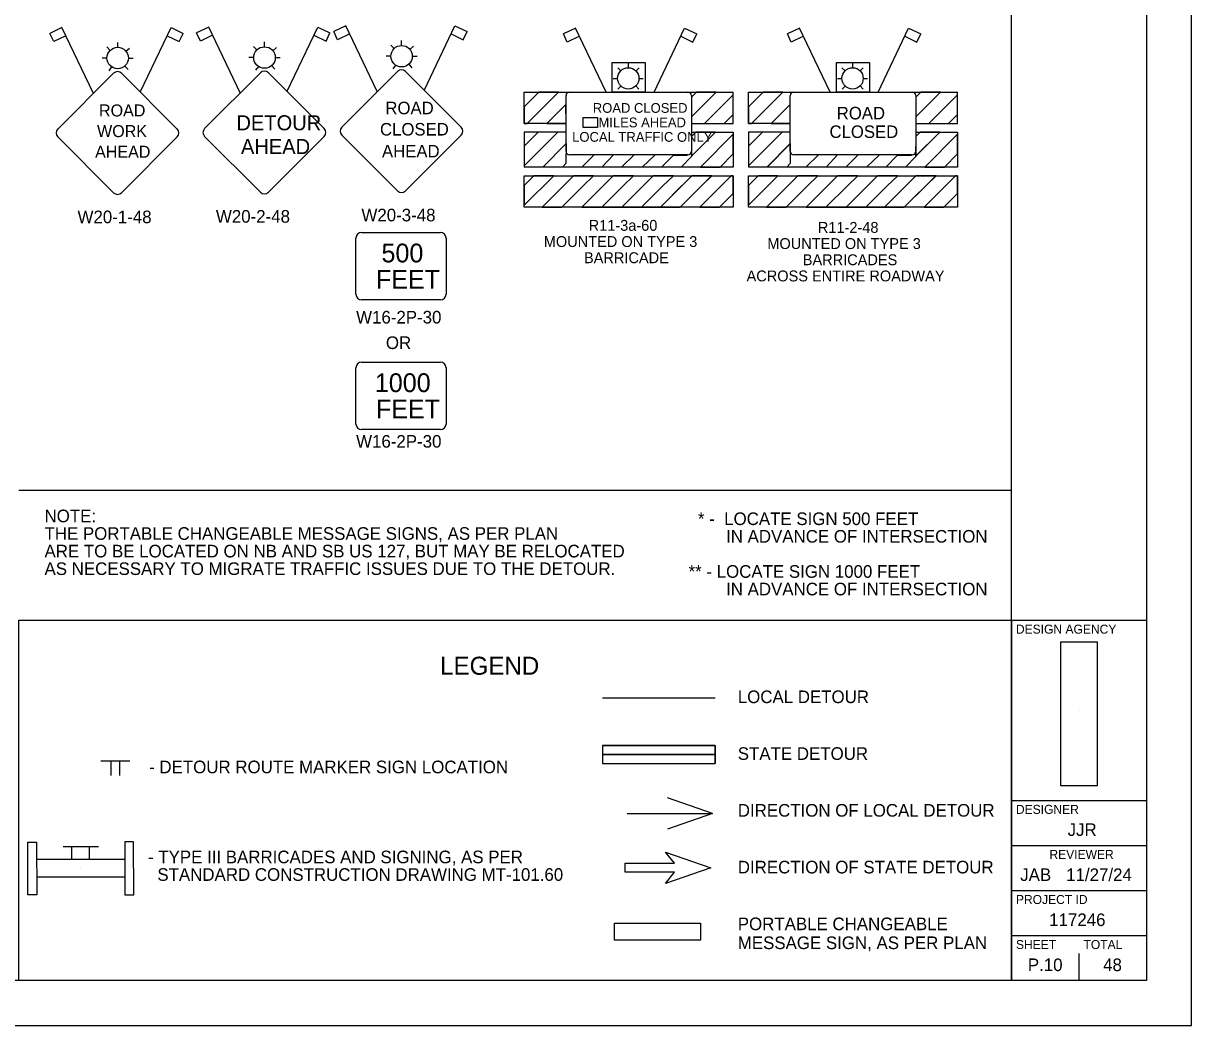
# Model space of a CAD drawing. Extents: x 1341221 to 1914484, y 79347 to 658398.
# Drawn here: x 1435873 to 1494221, y 559398 to 609451 of the extents above; entities that cross this region are included whole.
import ezdxf

# ---------------------------------------------------------------- set-up
doc = ezdxf.new("R2010")
doc.units = 0
for name, color, linetype in [('GM_X_County', 7, 'Continuous'), ('GM_X_County_Road_Text', 7, 'Continuous'), ('GM_X_Minor_Lake', 7, 'Continuous'), ('GM_X_Minor_Lake_Text', 7, 'Continuous'), ('GM_X_Minor_River', 7, 'Continuous'), ('GM_X_Minor_River_Text', 7, 'Continuous'), ('GM_X_State_Location', 7, 'Continuous'), ('GM_X_Township_Road_Text', 7, 'Continuous')]:
    doc.layers.add(name, color=color, linetype=linetype)

msp = doc.modelspace()

# ---------------------------------------------------------------- linework, layer by layer
at = {"layer": 'GM_X_County'}
for p, q in [((1437800, 609239), (1437194, 608949)), ((1439371, 605952), (1437800, 609239)), ((1441721, 606043), (1443249, 609239)), ((1443249, 609239), (1443856, 608949)), ((1445132, 609265), (1444525, 608975)), ((1446703, 605978), (1445132, 609265)), ((1449053, 606069), (1450581, 609265)), ((1450581, 609265), (1451187, 608975)), ((1451980, 609332), (1451373, 609042)), ((1453551, 606045), (1451980, 609332)), ((1455901, 606136), (1457428, 609332)), ((1457428, 609332), (1458035, 609042)), ((1463450, 609217), (1462844, 608927)), ((1464978, 606022), (1463450, 609217)), ((1467371, 606022), (1468899, 609217)), ((1468899, 609217), (1469506, 608927)), ((1474639, 609214), (1474033, 608924)), ((1476167, 606019), (1474639, 609214)), ((1478560, 606019), (1480088, 609214)), ((1480088, 609214), (1480695, 608924)), ((1437389, 608541), (1437194, 608949)), ((1437995, 608831), (1437389, 608541)), ((1443054, 608831), (1443661, 608541)), ((1443661, 608541), (1443856, 608949)), ((1444720, 608567), (1444525, 608975)), ((1445327, 608857), (1444720, 608567)), ((1450386, 608857), (1450992, 608567)), ((1450992, 608567), (1451187, 608975)), ((1451568, 608634), (1451373, 609042)), ((1452175, 608924), (1451568, 608634)), ((1454763, 608347), (1454763, 608588)), ((1457233, 608924), (1457840, 608634)), ((1457840, 608634), (1458035, 609042)), ((1463039, 608520), (1462844, 608927)), ((1463645, 608810), (1463039, 608520)), ((1468704, 608810), (1469311, 608520)), ((1469311, 608520), (1469506, 608927)), ((1474228, 608516), (1474033, 608924)), ((1474834, 608806), (1474228, 608516)), ((1479893, 608806), (1480500, 608516)), ((1480500, 608516), (1480695, 608924)), ((1440210, 608102), (1440041, 608275)), ((1440584, 608254), (1440584, 608496)), ((1440995, 608062), (1441180, 608216)), ((1447541, 608128), (1447373, 608300)), ((1447916, 608280), (1447916, 608521)), ((1448327, 608087), (1448512, 608242)), ((1454389, 608195), (1454221, 608367)), ((1455175, 608154), (1455360, 608309)), ((1440048, 607719), (1439807, 607719)), ((1441120, 607719), (1441361, 607719)), ((1447380, 607744), (1447139, 607744)), ((1448451, 607744), (1448693, 607744)), ((1454227, 607811), (1453986, 607811)), ((1455120, 607411), (1455280, 607231)), ((1455299, 607811), (1455540, 607811)), ((1466085, 607448), (1466087, 607229)), ((1477286, 607448), (1477288, 607230)), ((1440278, 607279), (1440140, 607081)), ((1440940, 607319), (1441101, 607139)), ((1447609, 607305), (1447472, 607107)), ((1448272, 607344), (1448433, 607164)), ((1454457, 607371), (1454319, 607173)), ((1465556, 607230), (1465709, 607077)), ((1466466, 607072), (1466620, 607228)), ((1476757, 607230), (1476910, 607077)), ((1477668, 607073), (1477821, 607228)), ((1465335, 606702), (1465553, 606703)), ((1465561, 606167), (1465715, 606323)), ((1466461, 606325), (1466614, 606172)), ((1466615, 606702), (1466833, 606704)), ((1476536, 606702), (1476755, 606703)), ((1476762, 606167), (1476916, 606323)), ((1477662, 606325), (1477815, 606172)), ((1477816, 606702), (1478035, 606704)), ((1460885, 605287), (1461613, 606018)), ((1461613, 606018), (1460885, 605287)), ((1461034, 604448), (1462599, 606018)), ((1461034, 604448), (1462599, 606018)), ((1462975, 603059), (1462975, 605847)), ((1463149, 606019), (1469067, 606018)), ((1463150, 606022), (1469065, 606022)), ((1468542, 606017), (1471327, 606018)), ((1469240, 605763), (1469491, 606018)), ((1469491, 606018), (1469240, 605763)), ((1469240, 605844), (1469240, 603060)), ((1469240, 605763), (1469241, 604780)), ((1469241, 604780), (1470478, 606018)), ((1469241, 604780), (1470478, 606018)), ((1470478, 606018), (1469491, 606018)), ((1469896, 604450), (1471329, 605886)), ((1471329, 605886), (1469896, 604450)), ((1471328, 604447), (1471327, 606018)), ((1471327, 604900), (1471329, 605886)), ((1472086, 605287), (1472814, 606018)), ((1472814, 606018), (1472086, 605287)), ((1472235, 604449), (1473801, 606018)), ((1472235, 604449), (1473801, 606018)), ((1474176, 603059), (1474177, 605847)), ((1474350, 606019), (1480268, 606018)), ((1474351, 606022), (1480266, 606022)), ((1479743, 606017), (1482528, 606018)), ((1480441, 605763), (1480693, 606018)), ((1480693, 606018), (1480441, 605763)), ((1480441, 605845), (1480441, 603060)), ((1480441, 605763), (1480442, 604780)), ((1480442, 604780), (1481679, 606018)), ((1480442, 604780), (1481679, 606018)), ((1481679, 606018), (1480693, 606018)), ((1481097, 604450), (1482530, 605886)), ((1482530, 605886), (1481097, 604450)), ((1482530, 604447), (1482528, 606018)), ((1482528, 604900), (1482530, 605886)), ((1462974, 605407), (1462018, 604450)), ((1462018, 604450), (1462974, 605407)), ((1462976, 604448), (1462974, 605407)), ((1474175, 605407), (1473219, 604450)), ((1473219, 604450), (1474175, 605407)), ((1474177, 604448), (1474175, 605407)), ((1470879, 604448), (1471327, 604900)), ((1470879, 604448), (1471327, 604900)), ((1482080, 604448), (1482528, 604900)), ((1482080, 604448), (1482528, 604900)), ((1462973, 604015), (1460887, 604013)), ((1460887, 603317), (1461584, 604015)), ((1461584, 604015), (1460887, 603317)), ((1460887, 604013), (1460888, 602274)), ((1460888, 602333), (1462567, 604013)), ((1460888, 602333), (1462567, 604013)), ((1462567, 604013), (1461584, 604015)), ((1469239, 602811), (1470445, 604014)), ((1469239, 603797), (1469459, 604013)), ((1469240, 604449), (1471328, 604447)), ((1469687, 602273), (1471327, 603914)), ((1471327, 603914), (1469687, 602273)), ((1469896, 604450), (1470879, 604448)), ((1472088, 603317), (1472785, 604015)), ((1472785, 604015), (1472088, 603317)), ((1474174, 604015), (1472089, 604013)), ((1472089, 602334), (1473768, 604014)), ((1472089, 602334), (1473768, 604014)), ((1472089, 604013), (1472089, 602274)), ((1473768, 604014), (1472785, 604015)), ((1480440, 603797), (1480660, 604014)), ((1480441, 602811), (1481646, 604014)), ((1480442, 604449), (1482530, 604447)), ((1480888, 602273), (1482528, 603914)), ((1482528, 603914), (1480888, 602273)), ((1481097, 604450), (1482080, 604448)), ((1482530, 604013), (1482530, 602275)), ((1460887, 603317), (1460888, 602333)), ((1461811, 602273), (1462973, 603438)), ((1472088, 603317), (1472089, 602334)), ((1473013, 602273), (1474174, 603438)), ((1469066, 602885), (1463148, 602885)), ((1470673, 602274), (1471328, 602930)), ((1470673, 602274), (1471328, 602930)), ((1480267, 602885), (1474349, 602886)), ((1481874, 602274), (1482529, 602930)), ((1481874, 602274), (1482529, 602930)), ((1468178, 602273), (1460888, 602274)), ((1469206, 602273), (1468178, 602273)), ((1479379, 602273), (1472089, 602274)), ((1480407, 602273), (1479379, 602273)), ((1460886, 600364), (1462361, 601840)), ((1460886, 600364), (1462361, 601840)), ((1460886, 601351), (1461375, 601839)), ((1461375, 601839), (1460886, 601351)), ((1461780, 600274), (1463345, 601841)), ((1463345, 601841), (1461780, 600274)), ((1464354, 601838), (1463345, 601841)), ((1463773, 600272), (1465338, 601839)), ((1465338, 601839), (1463773, 600272)), ((1463833, 601342), (1464354, 601838)), ((1466347, 601836), (1465338, 601839)), ((1465766, 600270), (1467330, 601837)), ((1467330, 601837), (1465766, 600270)), ((1465825, 601341), (1466347, 601836)), ((1468340, 601835), (1467330, 601837)), ((1469251, 601843), (1467687, 600276)), ((1467818, 601339), (1468340, 601835)), ((1468284, 600870), (1469253, 601839)), ((1468669, 600274), (1470240, 601839)), ((1470260, 601840), (1469251, 601843)), ((1469656, 600275), (1471223, 601838)), ((1471223, 601838), (1469656, 600275)), ((1469739, 601344), (1470260, 601840)), ((1472087, 600364), (1473562, 601840)), ((1472087, 600364), (1473562, 601840)), ((1472087, 601351), (1472576, 601839)), ((1472576, 601839), (1472087, 601351)), ((1472981, 600274), (1474546, 601841)), ((1474546, 601841), (1472981, 600274)), ((1475555, 601838), (1474546, 601841)), ((1474974, 600272), (1476539, 601839)), ((1476539, 601839), (1474974, 600272)), ((1475034, 601342), (1475555, 601838)), ((1477548, 601836), (1476539, 601839)), ((1476967, 600271), (1478532, 601838)), ((1478532, 601838), (1476967, 600271)), ((1477027, 601341), (1477548, 601836)), ((1479541, 601835), (1478532, 601838)), ((1480452, 601843), (1478888, 600276)), ((1479019, 601339), (1479541, 601835)), ((1479485, 600870), (1480454, 601839)), ((1479870, 600274), (1481441, 601840)), ((1481461, 601840), (1480452, 601843)), ((1480857, 600275), (1482424, 601838)), ((1482424, 601838), (1480857, 600275)), ((1480940, 601345), (1481461, 601840)), ((1462763, 600272), (1463833, 601342)), ((1464756, 600270), (1465825, 601341)), ((1466748, 600269), (1467818, 601339)), ((1468669, 600274), (1469739, 601344)), ((1473964, 600272), (1475034, 601342)), ((1475957, 600271), (1477027, 601341)), ((1477950, 600269), (1479019, 601339)), ((1479870, 600274), (1480940, 601345)), ((1470641, 600272), (1471327, 600961)), ((1470641, 600272), (1471327, 600961)), ((1481843, 600272), (1482528, 600961)), ((1481843, 600272), (1482528, 600961)), ((1461780, 600274), (1462763, 600272)), ((1463773, 600272), (1464756, 600270)), ((1464008, 600276), (1468005, 600273)), ((1465766, 600270), (1466748, 600269)), ((1467687, 600276), (1468669, 600274)), ((1472981, 600274), (1473964, 600272)), ((1474974, 600272), (1475957, 600271)), ((1475209, 600277), (1479206, 600274)), ((1476967, 600271), (1477950, 600269)), ((1478888, 600276), (1479870, 600274)), ((1464804, 575773), (1470429, 575773)), ((1464804, 573388), (1470429, 573388)), ((1464804, 573388), (1464804, 572488)), ((1470429, 573388), (1470429, 572488)), ((1464804, 572488), (1470429, 572488)), ((1470299, 569986), (1468049, 569205))]:
    msp.add_line(p, q, dxfattribs=at)
for points in [[(1465288, 607489), (1466926, 607489), (1466926, 606022), (1465288, 606022)], [(1476489, 607489), (1478128, 607489), (1478128, 606022), (1476489, 606022)], [(1463836, 604754), (1464542, 604754), (1464542, 604255), (1463836, 604255)], [(1469459, 604013), (1469239, 603797), (1469235, 602818), (1470445, 604014)], [(1480660, 604014), (1480440, 603797), (1480436, 602818), (1481646, 604014)], [(1461809, 602276), (1462976, 603449), (1462969, 602446), (1462798, 602273)], [(1473010, 602276), (1474177, 603450), (1474170, 602446), (1473999, 602273)], [(1464399, 602897), (1465355, 602899), (1464765, 602274), (1463757, 602274)], [(1465752, 602273), (1466389, 602902), (1467431, 602888), (1466781, 602273)], [(1468336, 602876), (1469016, 602876), (1469121, 602895), (1469182, 602935), (1469219, 602969), (1469237, 603026), (1469238, 602804), (1468722, 602273), (1467745, 602273)], [(1475600, 602897), (1476556, 602899), (1475966, 602274), (1474958, 602274)], [(1476953, 602274), (1477590, 602902), (1478632, 602888), (1477982, 602274)], [(1479537, 602876), (1480218, 602876), (1480323, 602895), (1480383, 602935), (1480420, 602969), (1480439, 603026), (1480439, 602805), (1479923, 602273), (1478946, 602273)], [(1489522, 571384), (1489522, 578543), (1487671, 578543), (1487671, 571384)], [(1470429, 573388), (1464804, 573388), (1464804, 572938), (1470429, 572938)], [(1464804, 572488), (1470429, 572488), (1470429, 572938), (1464804, 572938)]]:
    msp.add_lwpolyline(points, close=True, dxfattribs=at)
for points in [[(1460886, 606017), (1463670, 606018)], [(1462976, 604448), (1460888, 604450), (1460886, 606017)], [(1462599, 606018), (1461613, 606018)], [(1472087, 606018), (1474871, 606018)], [(1474177, 604448), (1472089, 604450), (1472087, 606018)], [(1473801, 606018), (1472814, 606018)], [(1460885, 605287), (1460888, 604450), (1461034, 604448)], [(1472086, 605287), (1472089, 604450), (1472235, 604449)], [(1462018, 604450), (1462976, 604448)], [(1469241, 604015), (1471329, 604013), (1471329, 602274), (1469206, 602273)], [(1471328, 602930), (1471327, 603914)], [(1473219, 604450), (1474177, 604448)], [(1480442, 604015), (1482530, 604013), (1482530, 602275), (1480407, 602273)], [(1482529, 602930), (1482528, 603914)], [(1469687, 602273), (1470673, 602274)], [(1480888, 602273), (1481874, 602274)], [(1460887, 601837), (1463835, 601838)], [(1468110, 600273), (1460887, 600274), (1460887, 601837)], [(1462361, 601840), (1461375, 601839)], [(1463245, 601838), (1471328, 601838), (1471329, 600274), (1468014, 600273)], [(1471327, 600961), (1471328, 601838), (1471223, 601838)], [(1472088, 601837), (1475036, 601838)], [(1479311, 600273), (1472088, 600274), (1472088, 601837)], [(1473562, 601840), (1472576, 601839)], [(1474446, 601838), (1482530, 601838), (1482530, 600274), (1479216, 600273)], [(1482528, 600961), (1482530, 601838), (1482424, 601838)], [(1460886, 601351), (1460886, 600364)], [(1472087, 601351), (1472087, 600364)], [(1469656, 600275), (1470641, 600272)], [(1480857, 600275), (1481843, 600272)], [(1466024, 569986), (1470299, 569986), (1468049, 570767)]]:
    msp.add_lwpolyline(points, dxfattribs=at)
for centre, radius in [((1440584, 607719), 536), ((1447916, 607744), 536), ((1454763, 607811), 536), ((1466085, 606701), 532), ((1477286, 606701), 532)]:
    msp.add_circle(centre, radius, dxfattribs=at)
for centre, start, end in [((1463149, 605845), 89.99972, 179.99972), ((1469066, 605845), 359.99972, 89.99972), ((1474350, 605846), 89.99972, 179.99972), ((1480268, 605846), 359.99972, 89.99972), ((1463149, 603061), 179.99972, 269.99972), ((1469066, 603061), 269.99972, 359.99972), ((1474350, 603061), 179.99972, 269.99972), ((1480268, 603061), 269.99972, 359.99972)]:
    msp.add_arc(centre, 174, start, end, dxfattribs=at)
at = {"layer": 'GM_X_County_Road_Text'}
for points in [[(1437594, 604175), (1440379, 606960)], [(1440776, 606960), (1443561, 604175)], [(1444926, 604201), (1447711, 606985)], [(1448108, 606985), (1450893, 604201)], [(1451774, 604268), (1454558, 607052)], [(1454956, 607052), (1457740, 604268)], [(1440379, 600993), (1437594, 603778)], [(1443561, 603778), (1440776, 600993)], [(1447711, 601019), (1444926, 603803)], [(1450893, 603803), (1448108, 601019)], [(1454558, 601086), (1451774, 603870)], [(1457740, 603870), (1454956, 601086)]]:
    msp.add_lwpolyline(points, dxfattribs=at)
msp.add_lwpolyline([(1465393, 564517), (1469696, 564517), (1469696, 563672), (1465393, 563672)], close=True, dxfattribs=at)
for centre, start, end in [((1440578, 606761), 45, 135), ((1447909, 606786), 45, 135), ((1454757, 606853), 45, 135), ((1437793, 603977), 135, 225), ((1443362, 603977), 315, 45), ((1445125, 604002), 135, 225), ((1450694, 604002), 315, 45), ((1451973, 604069), 135, 225), ((1457541, 604069), 315, 45), ((1440578, 601192), 225, 315), ((1447909, 601218), 225, 315), ((1454757, 601285), 225, 315)]:
    msp.add_arc(centre, 281, start, end, dxfattribs=at)
at = {"layer": 'GM_X_Minor_Lake'}
for p, q in [((1488596, 575148), (1488596, 575148)), ((1488596, 561648), (1488596, 562998)), ((1486908, 562436), (1486908, 562436))]:
    msp.add_line(p, q, dxfattribs=at)
at = {"layer": 'GM_X_Minor_Lake_Text'}
for p, q in [((1485221, 561648), (1485221, 656148)), ((1435650, 586144), (1485221, 586144)), ((1485221, 579648), (1491971, 579648)), ((1485221, 570648), (1491971, 570648)), ((1485221, 568398), (1491971, 568398)), ((1485221, 566148), (1491971, 566148)), ((1485221, 563898), (1491971, 563898))]:
    msp.add_line(p, q, dxfattribs=at)
for points in [[(1347971, 656148), (1491971, 656148), (1491971, 561648), (1347971, 561648)], [(1435649, 579648), (1485221, 579648), (1485221, 561648), (1435649, 561648)]]:
    msp.add_lwpolyline(points, close=True, dxfattribs=at)
at = {"layer": 'GM_X_Minor_River'}
for p, q in [((1439742, 572618), (1441182, 572618)), ((1440246, 572618), (1440246, 571898)), ((1440462, 572618), (1440462, 572618)), ((1440462, 572618), (1440462, 572618)), ((1440678, 572618), (1440678, 571898))]:
    msp.add_line(p, q, dxfattribs=at)
for points in [[(1452483, 595919), (1452483, 598731)], [(1452765, 599013), (1456702, 599013)], [(1456983, 598731), (1456983, 595919)], [(1456702, 595638), (1452765, 595638)], [(1452483, 589443), (1452483, 592256)], [(1452765, 592537), (1456702, 592537)], [(1456983, 592256), (1456983, 589443)], [(1456702, 589162), (1452765, 589162)]]:
    msp.add_lwpolyline(points, dxfattribs=at)
for centre, start, end in [((1452765, 598731), 90, 180), ((1456702, 598731), 0, 90), ((1452765, 595919), 180, 270), ((1456702, 595919), 270, 0), ((1452765, 592256), 90, 180), ((1456702, 592256), 0, 90), ((1452765, 589443), 180, 270), ((1456702, 589443), 270, 0)]:
    msp.add_arc(centre, 281, start, end, dxfattribs=at)
at = {"layer": 'GM_X_Minor_River_Text'}
msp.add_lwpolyline([(1341221, 559398), (1494221, 559398), (1494221, 658398), (1341221, 658398)], close=True, dxfattribs=at)
at = {"layer": 'GM_X_State_Location'}
msp.add_lwpolyline([(1470429, 572938), (1464804, 572938)], dxfattribs=at)
at = {"layer": 'GM_X_Township_Road_Text'}
for p, q in [((1437858, 568349), (1439619, 568352)), ((1438299, 567689), (1438298, 568350)), ((1439180, 567691), (1439179, 568351)), ((1468400, 567507), (1467950, 568063)), ((1467950, 568063), (1470200, 567282)), ((1440942, 567693), (1436537, 567687)), ((1438740, 567249), (1438740, 567249)), ((1465925, 567057), (1465925, 567507)), ((1465925, 567507), (1468400, 567507)), ((1465925, 567282), (1465925, 567282)), ((1470200, 567282), (1467950, 566501)), ((1470200, 567282), (1470200, 567282)), ((1440943, 566812), (1436539, 566806)), ((1468400, 567057), (1465925, 567057)), ((1467950, 566501), (1468400, 567057))]:
    msp.add_line(p, q, dxfattribs=at)
for points in [[(1436099, 565924), (1436096, 568567), (1436536, 568568), (1436540, 565925)], [(1441385, 565932), (1441381, 568575), (1440941, 568574), (1440944, 565931)]]:
    msp.add_lwpolyline(points, close=True, dxfattribs=at)

# ---------------------------------------------------------------- texts
at = {"layer": 'GM_X_County'}
for s, height, p in [('ROAD CLOSED', 485.96, (1464312, 604984)), ('ROAD', 624.1, (1476496, 604656)), ('   MILES AHEAD', 485.96, (1464053, 604261)), ('LOCAL TRAFFIC ONLY', 485.96, (1463282, 603538)), ('CLOSED', 624.1, (1476135, 603728)), ('R11-3a-60', 543, (1464106, 599091)), ('R11-2-48', 543, (1475554, 598990)), ('MOUNTED ON TYPE 3', 543.04, (1461865, 598283)), ('MOUNTED ON TYPE 3', 543.04, (1473029, 598182)), ('BARRICADE ', 543, (1463873, 597475)), ('BARRICADES ', 543.04, (1474799, 597374)), ('ACROSS ENTIRE ROADWAY', 543.04, (1471992, 596566))]:
    msp.add_text(s, height=height, rotation=359.99972, dxfattribs=at).set_placement(p)
for s, height, p in [('OR', 630, (1453978, 593187)), ('LEGEND', 900, (1456688, 576921)), ('LOCAL DETOUR', 630, (1471554, 575505)), ('STATE DETOUR', 630, (1471554, 572670)), ('DIRECTION OF LOCAL DETOUR', 630, (1471554, 569835)), ('DIRECTION OF STATE DETOUR', 630, (1471554, 567000)), ('PORTABLE CHANGEABLE ', 630, (1471554, 564165)), ('MESSAGE SIGN, AS PER PLAN', 630, (1471554, 563220))]:
    msp.add_text(s, height=height, dxfattribs=at).set_placement(p)
at = {"layer": 'GM_X_County_Road_Text'}
for s, height, p in [('ROAD', 599.7, (1439651, 604802)), ('ROAD', 625, (1453953, 604912)), ('DETOUR', 750, (1446515, 604111)), ('CLOSED', 625, (1453685, 603850)), ('WORK', 599.7, (1439553, 603770)), ('AHEAD', 599.7, (1439455, 602740)), ('AHEAD', 750, (1446740, 602924)), ('AHEAD', 625, (1453783, 602756)), ('W20-1-48', 630, (1438578, 599471)), ('W20-2-48', 630, (1445490, 599497)), ('W20-3-48', 630, (1452758, 599563)), ('W16-2P-30', 630, (1452492, 594462)), ('W16-2P-30', 630, (1452492, 588262)), ('NOTE:', 630, (1436929, 584537)), ('  * -  LOCATE SIGN 500 FEET', 630, (1469096, 584397)), ('THE PORTABLE CHANGEABLE MESSAGE SIGNS, AS PER PLAN', 630, (1436929, 583659)), ('        IN ADVANCE OF INTERSECTION', 630, (1469096, 583519)), ('ARE TO BE LOCATED ON NB AND SB US 127, BUT MAY BE RELOCATED ', 630, (1436929, 582781)), ('AS NECESSARY TO MIGRATE TRAFFIC ISSUES DUE TO THE DETOUR.', 630, (1436929, 581903)), ('** - LOCATE SIGN 1000 FEET', 630, (1469096, 581764)), ('        IN ADVANCE OF INTERSECTION', 630, (1469096, 580886)), ('- DETOUR ROUTE MARKER SIGN LOCATION', 630, (1442154, 572002)), ('- TYPE III BARRICADES AND SIGNING, AS PER ', 630, (1442098, 567507)), ('  STANDARD CONSTRUCTION DRAWING MT-101.60', 630, (1442098, 566629))]:
    msp.add_text(s, height=height, dxfattribs=at).set_placement(p)
at = {"layer": 'GM_X_Minor_Lake'}
for s, height, p in [('DESIGN AGENCY', 450, (1485446, 578973)), ('DESIGNER', 450, (1485446, 569973)), ('JJR', 630, (1488028, 568871)), ('REVIEWER', 450, (1487119, 567723)), ('JAB', 630, (1485660, 566621)), ('11/27/24', 630, (1487956, 566621)), ('PROJECT ID', 450, (1485446, 565473)), ('117246', 630, (1487107, 564371)), ('SHEET', 450, (1485446, 563223)), ('TOTAL', 450, (1488821, 563223)), ('P.10', 630, (1486041, 562121)), ('48', 630, (1489801, 562121))]:
    msp.add_text(s, height=height, dxfattribs=at).set_placement(p)
at = {"layer": 'GM_X_Minor_River'}
for s, p in [('500', (1453759, 597513)), ('FEET', (1453477, 596200)), ('1000', (1453427, 591037)), ('FEET', (1453477, 589725))]:
    msp.add_text(s, height=937.5, dxfattribs=at).set_placement(p)

doc.saveas('drawing.dxf')
